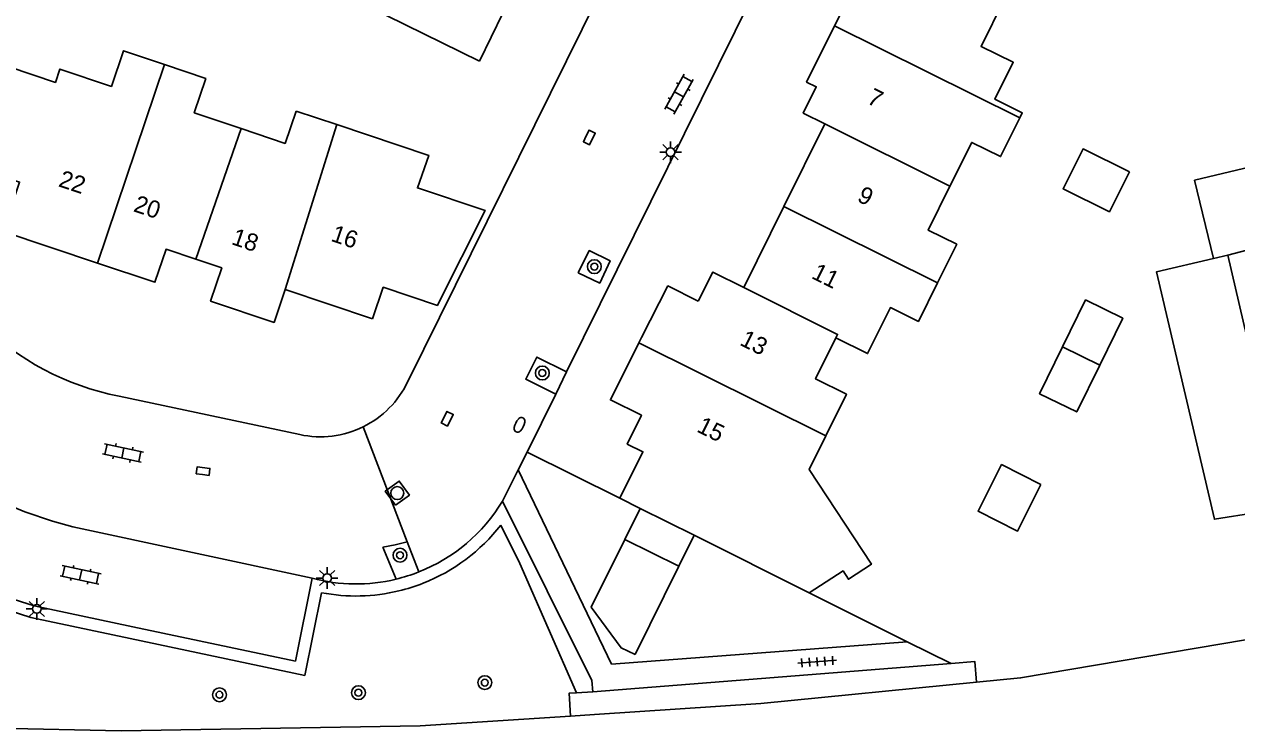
# Model space of a CAD drawing. Extents: x 136000 to 141000, y 400494 to 402006.
# Drawn here: x 137841.5 to 137911.7, y 401597.7 to 401638.7 of the extents above; entities that cross this region are included whole.
import ezdxf

# ---------------------------------------------------------------- set-up
doc = ezdxf.new("R2010")
doc.units = 0
for name, color, linetype in [('gg-afsc-erfafscheiding', 7, 'Continuous'), ('gg-anno-huisnummerreeks BGT', 7, 'Continuous'), ('gg-bbg-bijgebouw', 7, 'Continuous'), ('gg-bbg-gedigitaliseerde bebouwing', 7, 'Continuous'), ('gg-bbg-gedigitaliseerde bijgebouw', 7, 'Continuous'), ('gg-bbg-hoofdgebouw', 7, 'Continuous'), ('gg-bbg-luifel en loopbrug', 7, 'Continuous'), ('gg-bbg-tussenscheiding', 7, 'Continuous'), ('gg-knt-bronhoudergrens', 7, 'Continuous'), ('gg-knt-verharding', 7, 'Continuous'), ('gt-grn-groengrens', 7, 'Continuous'), ('gt-grn-weggrens', 7, 'Continuous'), ('gt-symb-boom', 7, 'Continuous'), ('gt-symb-brandkraan', 7, 'Continuous'), ('gt-symb-klinker verharding', 7, 'Continuous'), ('gt-symb-kolk', 7, 'Continuous'), ('gt-symb-lichtmast', 7, 'Continuous'), ('gt-symb-rioolschacht', 7, 'Continuous'), ('gt-symb-tegel verharding', 7, 'Continuous')]:
    doc.layers.add(name, color=color, linetype=linetype)

# ---------------------------------------------------------------- blocks, each defined once
blk = doc.blocks.new('gt0-BOOM')
at = {"layer": 'gt-symb-boom'}
for radius in [0.4, 0.2]:
    blk.add_circle((0, 0), radius, dxfattribs=at)
blk = doc.blocks.new('gt0-LMAST')
at = {"layer": 'gt-symb-lichtmast'}
for p, q in [((-0.182, 0.173), (-0.447, 0.438)), ((-0.005, 0.246), (-0.005, 0.621)), ((0.172, 0.173), (0.437, 0.438)), ((-0.255, -0.004), (-0.63, -0.004)), ((-0.182, -0.181), (-0.447, -0.446)), ((-0.005, -0.254), (-0.005, -0.629)), ((0.437, -0.446), (0.172, -0.181)), ((0.245, -0.004), (0.62, -0.004))]:
    blk.add_line(p, q, dxfattribs=at)
blk.add_circle((-0.005, -0.004), 0.25, dxfattribs=at)
blk = doc.blocks.new('gt0-KOLK')
at = {"layer": 'gt-symb-kolk'}
blk.add_lwpolyline([(0, 0), (0.375, 0), (0.375, 0.4), (-0.375, 0.4), (-0.375, 0), (0, 0)], dxfattribs=at)
blk = doc.blocks.new('gt0-KL1')
at = {"layer": 'gt-symb-klinker verharding'}
for p, q in [((-1.15, 0.3), (1.15, 0.3)), ((-1, -0.3), (-1, 0.3)), ((-0.5, 0.3), (-0.5, 0.45)), ((0, -0.3), (0, 0.3)), ((0.5, 0.3), (0.5, 0.45)), ((1, -0.3), (1, 0.3)), ((-1.15, -0.3), (1.15, -0.3)), ((-0.5, -0.45), (-0.5, -0.3)), ((0.5, -0.45), (0.5, -0.3))]:
    blk.add_line(p, q, dxfattribs=at)
blk = doc.blocks.new('gt0-TEG1')
at = {"layer": 'gt-symb-tegel verharding'}
for p, q in [((-1.125, 0), (1.125, 0)), ((-0.9, -0.25), (-0.9, 0.25)), ((-0.45, -0.25), (-0.45, 0.25)), ((0, -0.25), (0, 0.25)), ((0.45, -0.25), (0.45, 0.25)), ((0.9, -0.25), (0.9, 0.25))]:
    blk.add_line(p, q, dxfattribs=at)
blk = doc.blocks.new('gt0-BR')
at = {"layer": 'gt-symb-brandkraan'}
for centre, radius, start, end in [((-0.244, 0), 0.206, 107.56694, 252.43307), ((0.599, -2.664), 3, 106.89205, 107.56694), ((0, -0.691), 0.938, 73.10799, 106.89205), ((-0.599, -2.664), 3, 72.43309, 73.10799), ((0.244, 0), 0.206, 287.56695, 72.43309), ((0.599, 2.664), 3, 252.43307, 253.10797), ((0, 0.691), 0.938, 253.10797, 286.89206), ((-0.599, 2.664), 3, 286.89206, 287.56695)]:
    blk.add_arc(centre, radius, start, end, dxfattribs=at)
blk = doc.blocks.new('gt0-RS')
at = {"layer": 'gt-symb-rioolschacht'}
blk.add_lwpolyline([(-0.5, -0.5), (0.5, -0.5), (0.5, 0.5), (-0.5, 0.5)], close=True, dxfattribs=at)
blk.add_circle((0, 0), 0.375, dxfattribs=at)

msp = doc.modelspace()

# ---------------------------------------------------------------- linework, layer by layer
at = {"layer": 'gg-afsc-erfafscheiding'}
for p, q in [((137870.633, 401613.878), (137876, 401611.2)), ((137886.981, 401605.716), (137892.65, 401602.89)), ((137892.65, 401602.89), (137895.188, 401601.625))]:
    msp.add_line(p, q, dxfattribs=at)
msp.add_lwpolyline([(137912.888, 401610.381), (137910.438, 401609.983), (137907.08, 401624.313), (137910.382, 401625.087)], dxfattribs=at)
at = {"layer": 'gg-bbg-bijgebouw'}
msp.add_line((137910.382, 401625.087), (137911.21, 401625.281), dxfattribs=at)
msp.add_lwpolyline([(137918.035, 401627.072), (137916.985, 401631.468), (137909.296, 401629.631), (137910.382, 401625.087)], dxfattribs=at)
at = {"layer": 'gg-bbg-gedigitaliseerde bebouwing'}
for p, q in [((137867.88, 401636.53), (137862.501, 401639.178)), ((137880.306, 401609.067), (137886.981, 401605.716))]:
    msp.add_line(p, q, dxfattribs=at)
for points in [[(137899.176, 401633.249), (137899.317, 401633.533), (137897.73, 401634.319), (137898.79, 401636.46), (137896.928, 401637.382), (137898.271, 401640.097), (137897.338, 401640.559), (137898.64, 401643.188), (137893.2, 401645.89)], [(137840.639, 401636.198), (137843.323, 401635.293), (137843.586, 401636.071), (137846.564, 401635.067), (137847.26, 401637.129), (137849.644, 401636.325)], [(137849.644, 401636.325), (137852.029, 401635.521), (137851.361, 401633.539), (137854.072, 401632.625)], [(137854.072, 401632.625), (137856.625, 401631.764), (137857.256, 401633.637)], [(137895.126, 401629.277), (137896.387, 401631.822), (137898.06, 401630.994), (137899.176, 401633.249)], [(137894.408, 401623.68), (137895.515, 401625.916), (137893.866, 401626.732), (137895.126, 401629.277)], [(137894.408, 401623.68), (137893.302, 401621.445), (137891.674, 401622.251), (137890.356, 401619.588), (137888.52, 401620.497)], [(137887.933, 401614.82), (137889.125, 401617.228), (137887.34, 401618.112), (137888.52, 401620.497)], [(137886.981, 401605.716), (137888.933, 401606.995), (137889.25, 401606.512), (137890.573, 401607.379), (137886.97, 401612.875), (137887.933, 401614.82)]]:
    msp.add_lwpolyline(points, dxfattribs=at)
at = {"layer": 'gg-bbg-gedigitaliseerde bijgebouw'}
for p, q in [((137877.178, 401610.612), (137876.292, 401608.819)), ((137876.292, 401608.819), (137879.421, 401607.274)), ((137879.421, 401607.274), (137880.306, 401609.067))]:
    msp.add_line(p, q, dxfattribs=at)
for points in [[(137905.515, 401630.107), (137904.362, 401627.798), (137901.682, 401629.136), (137902.836, 401631.445), (137905.515, 401630.107)], [(137903.801, 401618.917), (137905.134, 401621.634), (137902.982, 401622.689), (137901.65, 401619.972)], [(137901.65, 401619.972), (137900.317, 401617.255), (137902.469, 401616.2), (137903.801, 401618.917)], [(137900.398, 401612.002), (137898.114, 401613.149), (137896.759, 401610.45), (137899.043, 401609.303), (137900.398, 401612.002)]]:
    msp.add_lwpolyline(points, dxfattribs=at)
at = {"layer": 'gg-bbg-hoofdgebouw'}
for p, q in [((137890.96, 401643.65), (137888.44, 401638.57)), ((137857.256, 401633.637), (137859.613, 401632.849)), ((137887.874, 401632.902), (137885.504, 401628.115)), ((137885.504, 401628.115), (137883.18, 401623.42)), ((137856.628, 401623.304), (137861.68, 401621.6)), ((137877.27, 401620.52), (137877.114, 401620.209)), ((137876, 401611.2), (137877.178, 401610.612))]:
    msp.add_line(p, q, dxfattribs=at)
for points in [[(137866.109, 401640.857), (137869.24, 401639.3), (137867.88, 401636.53)], [(137888.44, 401638.57), (137886.827, 401635.319), (137887.383, 401635.043), (137886.627, 401633.52), (137887.874, 401632.902)], [(137859.613, 401632.849), (137864.941, 401631.067), (137864.29, 401629.182), (137868.205, 401627.878), (137865.479, 401622.469), (137865.446, 401622.374), (137862.308, 401623.425), (137861.68, 401621.6)], [(137838.654, 401630.405), (137841.25, 401629.52), (137840.29, 401626.65), (137845.765, 401624.825)], [(137845.765, 401624.825), (137849.08, 401623.72), (137849.73, 401625.63), (137851.448, 401625.051)], [(137851.448, 401625.051), (137852.952, 401624.544), (137852.306, 401622.629), (137855.983, 401621.39), (137856.628, 401623.304)], [(137911.21, 401625.281), (137912.553, 401619.546), (137916.448, 401620.458), (137917.628, 401615.414), (137927.032, 401617.615), (137926.974, 401617.904), (137929.517, 401618.533), (137929.351, 401619.051), (137929.088, 401618.988), (137928.434, 401621.724)], [(137883.18, 401623.42), (137881.39, 401624.31), (137880.552, 401622.627)], [(137877.27, 401620.52), (137878.795, 401623.502), (137880.552, 401622.627)], [(137877.114, 401620.209), (137875.46, 401616.9), (137877.26, 401616.01), (137876.44, 401614.34), (137877.34, 401613.9), (137876, 401611.2)]]:
    msp.add_lwpolyline(points, dxfattribs=at)
at = {"layer": 'gg-bbg-luifel en loopbrug'}
msp.add_line((137876.887, 401602.144), (137879.421, 401607.274), dxfattribs=at)
msp.add_lwpolyline([(137876.292, 401608.819), (137874.349, 401604.883), (137876.084, 401602.532), (137876.887, 401602.144)], dxfattribs=at)
at = {"layer": 'gg-bbg-tussenscheiding'}
for p, q in [((137888.44, 401638.57), (137899.176, 401633.249)), ((137845.765, 401624.825), (137849.644, 401636.325)), ((137851.448, 401625.051), (137854.072, 401632.625)), ((137856.628, 401623.304), (137859.613, 401632.849)), ((137887.874, 401632.902), (137895.126, 401629.277)), ((137885.504, 401628.115), (137894.408, 401623.68)), ((137911.21, 401625.281), (137918.035, 401627.072)), ((137877.114, 401620.209), (137887.933, 401614.82)), ((137901.65, 401619.972), (137903.801, 401618.917)), ((137877.178, 401610.612), (137880.306, 401609.067))]:
    msp.add_line(p, q, dxfattribs=at)
msp.add_lwpolyline([(137883.18, 401623.42), (137888.616, 401620.691), (137888.52, 401620.497)], dxfattribs=at)
at = {"layer": 'gg-knt-bronhoudergrens'}
for p, q in [((137874.534, 401598.673), (137873.159, 401598.583)), ((137847.136, 401597.729), (137828.644, 401598.126))]:
    msp.add_line(p, q, dxfattribs=at)
for points in [[(137936.993, 401607.793), (137918.069, 401603.99), (137899.215, 401600.795), (137896.666, 401600.542)], [(137896.666, 401600.542), (137884.175, 401599.304), (137874.534, 401598.673)], [(137873.159, 401598.583), (137864.444, 401598.014), (137847.136, 401597.729)]]:
    msp.add_lwpolyline(points, dxfattribs=at)
at = {"layer": 'gg-knt-verharding'}
for p, q in [((137863.73, 401617.96), (137889.28, 401669.641)), ((137872.928, 401618.523), (137883.867, 401640.667)), ((137872.294, 401617.24), (137872.928, 401618.523)), ((137847.01, 401617.11), (137857.482, 401614.889)), ((137870.633, 401613.878), (137872.294, 401617.24)), ((137870.633, 401613.878), (137870.113, 401612.839)), ((137870.113, 401612.839), (137869.206, 401611.029)), ((137863.69, 401608.675), (137864.362, 401606.929)), ((137862.292, 401608.371), (137863.046, 401606.513)), ((137840.068, 401605.614), (137842.083, 401604.961)), ((137847.802, 401603.755), (137842.083, 401604.961)), ((137895.188, 401601.625), (137874.448, 401599.994))]:
    msp.add_line(p, q, dxfattribs=at)
for points in [[(137873.591, 401624.267), (137874.841, 401623.67), (137875.441, 401624.959), (137874.234, 401625.555), (137873.591, 401624.267)], [(137872.294, 401617.24), (137870.556, 401618.098), (137871.192, 401619.381), (137872.928, 401618.523)], [(137870.113, 401612.839), (137875.528, 401601.589), (137892.65, 401602.89)], [(137874.448, 401599.994), (137874.377, 401600.636), (137869.206, 401611.029)], [(137841.542, 401610.423), (137843.153, 401609.867), (137844.339, 401609.538), (137858.192, 401606.568)], [(137863.69, 401608.675), (137862.996, 401608.496), (137862.292, 401608.371)], [(137858.192, 401606.568), (137857.218, 401601.769), (137847.802, 401603.755)]]:
    msp.add_lwpolyline(points, dxfattribs=at)
for centre, radius, start, end in [((137850.143, 401632.819), 16.018, 225.57528, 258.72015), ((137858.664, 401620.377), 5.613, 296.16362, 334.49595), ((137858.663, 401620.375), 5.612, 257.84998, 296.18017), ((137850.096, 401632.595), 23.765, 229.79877, 248.90406), ((137860.732, 401616.13), 9.891, 291.53277, 328.95691), ((137860.728, 401616.125), 9.888, 255.14169, 283.55995), ((137860.765, 401616.018), 9.774, 283.4937, 291.59077)]:
    msp.add_arc(centre, radius, start, end, dxfattribs=at)
at = {"layer": 'gt-grn-groengrens'}
for p, q in [((137870.224, 401607.411), (137869.11, 401609.651)), ((137870.224, 401607.411), (137873.494, 401599.932)), ((137839.191, 401605.162), (137841.902, 401604.284)), ((137847.658, 401603.07), (137841.902, 401604.284)), ((137873.494, 401599.932), (137874.448, 401599.994))]:
    msp.add_line(p, q, dxfattribs=at)
for points in [[(137858.735, 401605.726), (137857.764, 401600.938), (137847.658, 401603.07)], [(137895.188, 401601.625), (137896.573, 401601.734), (137896.666, 401600.542)], [(137873.494, 401599.932), (137873.073, 401599.904), (137873.159, 401598.583)]]:
    msp.add_lwpolyline(points, dxfattribs=at)
for centre, radius, start, end in [((137860.731, 401616.129), 10.591, 291.54058, 322.289), ((137860.771, 401616.018), 10.474, 283.46824, 291.56345), ((137860.725, 401616.114), 10.577, 259.15315, 283.58629)]:
    msp.add_arc(centre, radius, start, end, dxfattribs=at)
at = {"layer": 'gt-grn-weggrens'}
msp.add_line((137861.139, 401615.339), (137863.69, 401608.675), dxfattribs=at)

# ---------------------------------------------------------------- block references
at = {"layer": 'gt-symb-boom'}
for p in [(137874.532, 401624.621), (137871.519, 401618.458), (137863.278, 401607.9), (137860.87, 401599.936), (137868.188, 401600.518), (137852.822, 401599.814)]:
    msp.add_blockref('gt0-BOOM', p, dxfattribs=at)
at = {"layer": 'gt-symb-brandkraan', "rotation": 63.71668708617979}
msp.add_blockref('gt0-BR', (137870.197, 401615.452), dxfattribs=at)
at = {"layer": 'gt-symb-klinker verharding'}
for p, rotation in [((137879.438, 401634.613), 61.05113835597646), ((137847.228, 401613.825), 167.99329169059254), ((137844.781, 401606.765), 167.93725397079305)]:
    msp.add_blockref('gt0-KL1', p, dxfattribs=dict(at, rotation=rotation))
at = {"layer": 'gt-symb-kolk'}
for p, rotation in [((137874.061, 401632.197), -116.36005821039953), ((137865.832, 401615.901), -116.36005820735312), ((137851.849, 401612.576), -7.1818785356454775)]:
    msp.add_blockref('gt0-KOLK', p, dxfattribs=dict(at, rotation=rotation))
at = {"layer": 'gt-symb-lichtmast'}
for p in [(137878.952, 401631.252), (137859.058, 401606.583), (137842.252, 401604.79)]:
    msp.add_blockref('gt0-LMAST', p, dxfattribs=at)
at = {"layer": 'gt-symb-rioolschacht', "rotation": 36.01052540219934}
msp.add_blockref('gt0-RS', (137863.12, 401611.499), dxfattribs=at)
at = {"layer": 'gt-symb-tegel verharding', "rotation": 4.359151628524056}
msp.add_blockref('gt0-TEG1', (137887.436, 401601.73), dxfattribs=at)

# ---------------------------------------------------------------- texts
at = {"layer": 'gg-anno-huisnummerreeks BGT'}
for s, rotation, p in [('7', 333.6, (137890.261, 401634.115)), ('22', 341.6, (137843.446, 401629.287)), ('9', 333.6, (137889.694, 401628.439)), ('20', 341.6, (137847.788, 401627.84)), ('16', 341.3, (137859.222, 401626.123)), ('18', 341.4, (137853.46, 401625.933)), ('11', 333.6, (137887.051, 401623.974)), ('13', 333.5, (137882.899, 401620.108)), ('15', 333.7, (137880.406, 401615.086))]:
    msp.add_text(s, height=1, rotation=rotation, dxfattribs=at).set_placement(p)

doc.saveas('drawing.dxf')
